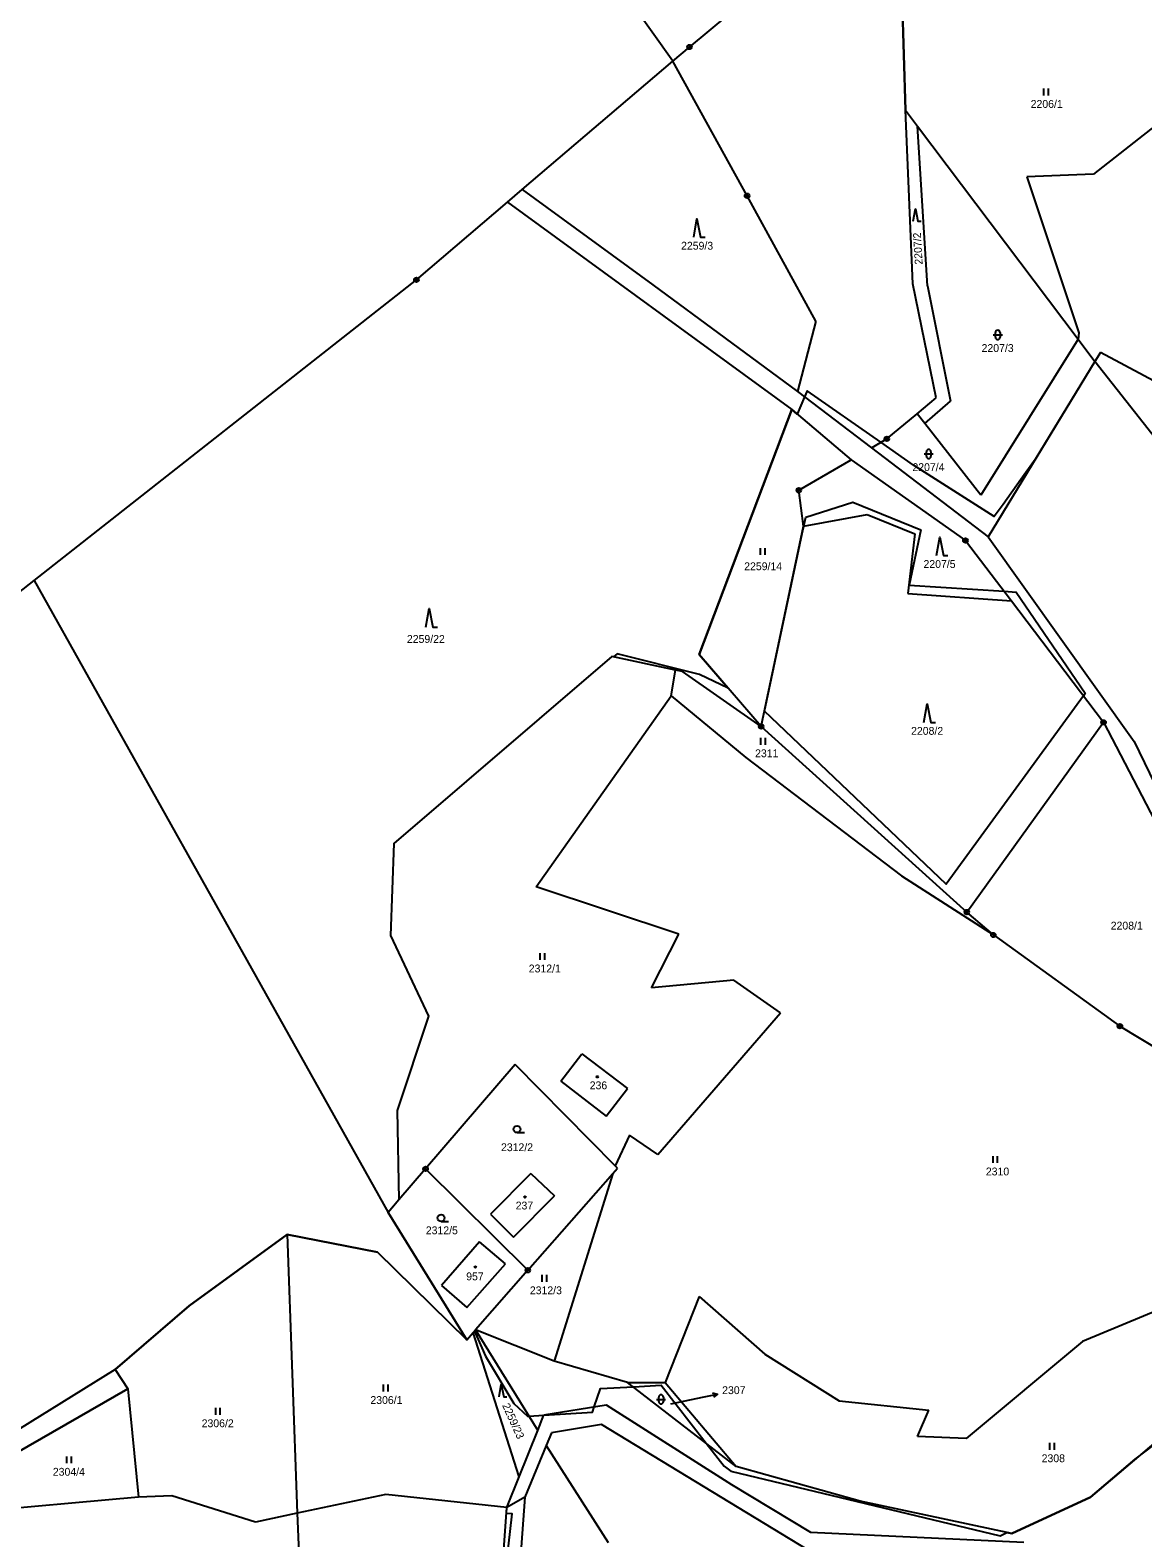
# Model space of a CAD drawing. Extents: x -439246 to -433691, y -1130252 to -1121148.
# Drawn here: x -435681.5 to -435440.1, y -1125991.2 to -1125664.2 of the extents above; entities that cross this region are included whole.
import ezdxf

# ---------------------------------------------------------------- set-up
doc = ezdxf.new("R2010")
doc.units = 0
for name, color, linetype in [('Vrstva 1', 7, 'Continuous'), ('Vrstva 16', 7, 'Continuous'), ('Vrstva 18', 7, 'Continuous'), ('Vrstva 19', 7, 'Continuous'), ('Vrstva 24', 7, 'Continuous'), ('Vrstva 25', 7, 'Continuous'), ('Vrstva 3', 7, 'Continuous'), ('Vrstva 37', 7, 'Continuous'), ('Vrstva 52', 7, 'Continuous'), ('Vrstva 6', 7, 'Continuous')]:
    doc.layers.add(name, color=color, linetype=linetype)

msp = doc.modelspace()

# ---------------------------------------------------------------- linework, layer by layer
at = {"layer": 'Vrstva 1'}
for p, q in [((-435576.26, -1125888.52), (-435595.7, -1125911.15)), ((-435595.7, -1125911.15), (-435601.48, -1125917.89)), ((-435595.7, -1125911.15), (-435573.53, -1125933.14)), ((-435576.65, -1125925.96), (-435567.77, -1125917.01)), ((-435584, -1125926.98), (-435592.25, -1125936.45)), ((-435578.37, -1125931.71), (-435584, -1125926.98)), ((-435586.77, -1125941.22), (-435578.37, -1125931.71)), ((-435592.25, -1125936.45), (-435586.77, -1125941.22))]:
    msp.add_line(p, q, dxfattribs=at)
for points in [[(-435538.46, -1125667.89), (-435508.19, -1125642.69)], [(-435491.59, -1125681.62), (-435492.33, -1125657.5)], [(-435542.09, -1125670.98), (-435538.46, -1125667.89)], [(-435574.76, -1125698.81), (-435542.09, -1125670.98)], [(-435525.97, -1125700.15), (-435542.09, -1125670.98)], [(-435428.66, -1125678.06), (-435450.83, -1125695.45)], [(-435489.99, -1125719.21), (-435491.59, -1125681.62)], [(-435491.59, -1125681.62), (-435488.98, -1125685.08)], [(-435486.84, -1125719.65), (-435488.98, -1125685.08)], [(-435488.98, -1125685.08), (-435454.19, -1125731.24)], [(-435450.83, -1125695.45), (-435465.3, -1125696.06)], [(-435465.3, -1125696.06), (-435454.05, -1125729.85)], [(-435577.96, -1125701.55), (-435574.76, -1125698.81)], [(-435574.76, -1125698.81), (-435546.39, -1125719.49)], [(-435511.08, -1125727.35), (-435525.97, -1125700.15)], [(-435597.71, -1125718.37), (-435577.96, -1125701.55)], [(-435577.96, -1125701.55), (-435516.29, -1125746.48)], [(-435680.62, -1125783.58), (-435597.71, -1125718.37)], [(-435546.39, -1125719.49), (-435515.07, -1125742.59)], [(-435484.97, -1125743.98), (-435489.99, -1125719.21)], [(-435486.84, -1125719.65), (-435481.83, -1125744.68)], [(-435511.08, -1125727.35), (-435515.07, -1125742.59)], [(-435454.05, -1125729.85), (-435454.19, -1125731.24)], [(-435454.19, -1125731.24), (-435475.24, -1125765.04)], [(-435454.19, -1125731.24), (-435450.52, -1125736.1)], [(-435450.52, -1125736.1), (-435473.69, -1125774.07)], [(-435449.32, -1125734.13), (-435450.52, -1125736.1)], [(-435420.97, -1125773.59), (-435450.52, -1125736.1)], [(-435434.6, -1125741.99), (-435449.32, -1125734.13)], [(-435515.07, -1125742.59), (-435499.01, -1125754.8)], [(-435536.34, -1125799.64), (-435516.29, -1125746.48)], [(-435516.29, -1125746.48), (-435503.38, -1125757.39)], [(-435489.1, -1125747.4), (-435484.97, -1125743.98)], [(-435487.42, -1125749.53), (-435481.83, -1125744.68)], [(-435495.67, -1125752.85), (-435489.1, -1125747.4)], [(-435487.42, -1125749.53), (-435489.1, -1125747.4)], [(-435475.24, -1125765.04), (-435487.42, -1125749.53)], [(-435499.01, -1125754.8), (-435495.67, -1125752.85)], [(-435499.01, -1125754.8), (-435473.69, -1125774.07)], [(-435514.75, -1125764.01), (-435503.38, -1125757.39)], [(-435503.38, -1125757.39), (-435478.61, -1125774.89)], [(-435513.71, -1125771.79), (-435514.75, -1125764.01)], [(-435513.71, -1125771.79), (-435499.9, -1125769.24)], [(-435499.9, -1125769.24), (-435489.61, -1125773.47)], [(-435522.92, -1125815.22), (-435513.71, -1125771.79)], [(-435489.61, -1125773.47), (-435491.13, -1125786.36)], [(-435478.61, -1125774.89), (-435468.65, -1125788)], [(-435473.69, -1125774.07), (-435441.99, -1125818.47)], [(-435759.66, -1125845.74), (-435680.62, -1125783.58)], [(-435491.13, -1125786.36), (-435468.65, -1125788)], [(-435468.65, -1125788), (-435448.64, -1125814.32)], [(-435555.28, -1125800.04), (-435602.61, -1125840.57)], [(-435541.53, -1125802.99), (-435555.28, -1125800.04)], [(-435522.92, -1125815.22), (-435536.34, -1125799.64)], [(-435542.42, -1125808.56), (-435541.53, -1125802.99)], [(-435539.96, -1125803.32), (-435541.53, -1125802.99)], [(-435522.92, -1125815.22), (-435539.96, -1125803.32)], [(-435571.69, -1125849.99), (-435542.42, -1125808.56)], [(-435542.42, -1125808.56), (-435526.21, -1125821.97)], [(-435522.92, -1125815.22), (-435478.3, -1125855.47)], [(-435478.3, -1125855.47), (-435448.64, -1125814.32)], [(-435448.64, -1125814.32), (-435432.88, -1125844.58)], [(-435441.99, -1125818.47), (-435430.93, -1125841.35)], [(-435526.21, -1125821.97), (-435492.49, -1125847.63)], [(-435602.61, -1125840.57), (-435603.35, -1125860.57)], [(-435492.49, -1125847.63), (-435472.56, -1125860.44)], [(-435540.76, -1125860.27), (-435571.69, -1125849.99)], [(-435472.56, -1125860.44), (-435478.3, -1125855.47)], [(-435603.35, -1125860.57), (-435595.11, -1125878.07)], [(-435546.74, -1125871.89), (-435540.76, -1125860.27)], [(-435472.56, -1125860.44), (-435445.11, -1125880.21)], [(-435528.87, -1125870.22), (-435546.74, -1125871.89)], [(-435518.73, -1125877.3), (-435528.87, -1125870.22)], [(-435545.35, -1125908.04), (-435518.73, -1125877.3)], [(-435595.11, -1125878.07), (-435601.87, -1125898.53)], [(-435445.11, -1125880.21), (-435427.6, -1125890.78)], [(-435566.36, -1125892.17), (-435561.79, -1125886.2)], [(-435561.79, -1125886.2), (-435551.94, -1125893.75)], [(-435554.6, -1125910.48), (-435576.26, -1125888.52)], [(-435566.36, -1125892.17), (-435556.51, -1125899.71)], [(-435556.51, -1125899.71), (-435551.94, -1125893.75)], [(-435601.87, -1125898.53), (-435601.48, -1125917.89)], [(-435551.5, -1125903.83), (-435554.6, -1125910.48)], [(-435545.35, -1125908.04), (-435551.5, -1125903.83)], [(-435572.86, -1125912.14), (-435581.65, -1125921)], [(-435573.53, -1125933.14), (-435555.12, -1125912.19)], [(-435572.86, -1125912.14), (-435567.77, -1125917.01)], [(-435555.12, -1125912.19), (-435567.84, -1125952.88)], [(-435555.12, -1125912.19), (-435554.08, -1125911.01)], [(-435554.08, -1125911.01), (-435554.6, -1125910.48)], [(-435601.48, -1125917.89), (-435603.81, -1125920.6)], [(-435586.75, -1125948.19), (-435603.81, -1125920.6)], [(-435581.65, -1125921), (-435576.65, -1125925.96)], [(-435646.98, -1125940.87), (-435625.72, -1125925.4)], [(-435625.72, -1125925.4), (-435623.54, -1125985.84)], [(-435625.72, -1125925.4), (-435606.15, -1125929.23)], [(-435606.15, -1125929.23), (-435586.75, -1125948.19)], [(-435573.53, -1125933.14), (-435584.85, -1125946.03)], [(-435536.36, -1125938.82), (-435543.73, -1125957.44)], [(-435536.36, -1125938.82), (-435522.1, -1125951.33)], [(-435663.03, -1125954.68), (-435646.98, -1125940.87)], [(-435436.19, -1125941.5), (-435453.19, -1125948.62)], [(-435585.36, -1125946.62), (-435584.85, -1125946.03)], [(-435567.84, -1125952.88), (-435584.85, -1125946.03)], [(-435586.75, -1125948.19), (-435585.36, -1125946.62)], [(-435575.43, -1125977.94), (-435585.36, -1125946.62)], [(-435453.19, -1125948.62), (-435478.46, -1125969.6)], [(-435522.1, -1125951.33), (-435505.97, -1125961.43)], [(-435663.03, -1125954.68), (-435700.15, -1125977.67)], [(-435663.03, -1125954.68), (-435660.33, -1125958.87)], [(-435551.89, -1125957.44), (-435567.84, -1125952.88)], [(-435695.43, -1125979.03), (-435660.33, -1125958.87)], [(-435660.33, -1125958.87), (-435657.96, -1125982.32)], [(-435528.35, -1125975.68), (-435551.89, -1125957.44)], [(-435551.89, -1125957.44), (-435543.73, -1125957.44)], [(-435543.73, -1125957.44), (-435528.35, -1125975.68)], [(-435423.08, -1125958.3), (-435451.48, -1125982.31)], [(-435570.05, -1125964.52), (-435556.53, -1125962.34)], [(-435556.53, -1125962.34), (-435529.39, -1125979.58)], [(-435505.97, -1125961.43), (-435486.53, -1125963.44)], [(-435571.39, -1125967.86), (-435570.05, -1125964.52)], [(-435489.02, -1125969.17), (-435486.53, -1125963.44)], [(-435575.43, -1125977.94), (-435571.39, -1125967.86)], [(-435568.42, -1125968.42), (-435569.54, -1125971.11)], [(-435557.58, -1125966.57), (-435568.42, -1125968.42)], [(-435512.96, -1125993.68), (-435557.58, -1125966.57)], [(-435569.54, -1125971.11), (-435574.21, -1125982.33)], [(-435478.46, -1125969.6), (-435489.02, -1125969.17)], [(-435578.1, -1125984.61), (-435575.43, -1125977.94)], [(-435501.45, -1125983.23), (-435528.35, -1125975.68)], [(-435604.33, -1125981.77), (-435623.54, -1125985.84)], [(-435578.1, -1125984.61), (-435604.33, -1125981.77)], [(-435529.39, -1125979.58), (-435512.24, -1125989.96)], [(-435657.96, -1125982.32), (-435695.01, -1125985.67)], [(-435650.77, -1125982.03), (-435657.96, -1125982.32)], [(-435632.62, -1125987.76), (-435650.77, -1125982.03)], [(-435580.5, -1126018.03), (-435578.1, -1125984.61)], [(-435574.21, -1125982.33), (-435578.1, -1125984.61)], [(-435574.21, -1125982.33), (-435576.14, -1126008.92)], [(-435468.57, -1125990.23), (-435501.45, -1125983.23)], [(-435451.48, -1125982.31), (-435468.57, -1125990.23)], [(-435623.54, -1125985.84), (-435632.62, -1125987.76)], [(-435623.54, -1125985.84), (-435618.51, -1126106.18)], [(-435512.24, -1125989.96), (-435465.95, -1125992.09)]]:
    msp.add_lwpolyline(points, dxfattribs=at)
at = {"layer": 'Vrstva 16'}
msp.add_line((-435535.31, -1125960.61), (-435532.38, -1125959.99), dxfattribs=at)
for points in [[(-435542.48, -1125962.13), (-435535.31, -1125960.61)], [(-435533.46, -1125959.71), (-435532.38, -1125959.99), (-435533.25, -1125960.68)]]:
    msp.add_lwpolyline(points, dxfattribs=at)
at = {"layer": 'Vrstva 24'}
for centre, radius in [((-435538.46, -1125667.89), 0.5), ((-435538.46, -1125667.89), 0.1), ((-435525.97, -1125700.15), 0.5), ((-435525.97, -1125700.15), 0.1), ((-435597.71, -1125718.37), 0.5), ((-435597.71, -1125718.37), 0.1), ((-435495.67, -1125752.85), 0.5), ((-435495.67, -1125752.85), 0.1), ((-435514.75, -1125764.01), 0.5), ((-435514.75, -1125764.01), 0.1), ((-435478.61, -1125774.89), 0.5), ((-435478.61, -1125774.89), 0.1), ((-435522.92, -1125815.22), 0.5), ((-435522.92, -1125815.22), 0.1), ((-435448.64, -1125814.32), 0.5), ((-435448.64, -1125814.32), 0.1), ((-435478.3, -1125855.47), 0.5), ((-435478.3, -1125855.47), 0.1), ((-435472.56, -1125860.44), 0.5), ((-435472.56, -1125860.44), 0.1), ((-435445.11, -1125880.21), 0.5), ((-435445.11, -1125880.21), 0.1), ((-435595.7, -1125911.15), 0.5), ((-435595.7, -1125911.15), 0.1), ((-435573.53, -1125933.14), 0.5), ((-435573.53, -1125933.14), 0.1)]:
    msp.add_circle(centre, radius, dxfattribs=at)
at = {"layer": 'Vrstva 25'}
for p, q in [((-435461.63, -1125678.39), (-435461.63, -1125676.89)), ((-435460.63, -1125678.39), (-435460.63, -1125676.89)), ((-435472.1, -1125730.82), (-435472.1, -1125729.82)), ((-435471.1, -1125729.82), (-435471.1, -1125730.82)), ((-435472.6, -1125730.32), (-435470.6, -1125730.32)), ((-435487.59, -1125756.14), (-435485.59, -1125756.14)), ((-435487.09, -1125756.64), (-435487.09, -1125755.64)), ((-435486.09, -1125755.64), (-435486.09, -1125756.64)), ((-435523.08, -1125778.04), (-435523.08, -1125776.54)), ((-435522.08, -1125778.04), (-435522.08, -1125776.54)), ((-435522.99, -1125819.19), (-435522.99, -1125817.69)), ((-435521.99, -1125819.19), (-435521.99, -1125817.69)), ((-435570.85, -1125865.85), (-435570.85, -1125864.35)), ((-435569.85, -1125865.85), (-435569.85, -1125864.35)), ((-435575.88, -1125903.3), (-435574.28, -1125903.3)), ((-435472.63, -1125909.87), (-435472.63, -1125908.37)), ((-435471.63, -1125909.87), (-435471.63, -1125908.37)), ((-435592.35, -1125922.55), (-435590.75, -1125922.55)), ((-435570.39, -1125935.64), (-435570.39, -1125934.14)), ((-435569.39, -1125935.64), (-435569.39, -1125934.14)), ((-435604.86, -1125959.43), (-435604.86, -1125957.93)), ((-435603.86, -1125959.43), (-435603.86, -1125957.93)), ((-435545.64, -1125961.13), (-435543.64, -1125961.13)), ((-435545.14, -1125961.63), (-435545.14, -1125960.63)), ((-435544.14, -1125960.63), (-435544.14, -1125961.63)), ((-435641.24, -1125964.47), (-435641.24, -1125962.97)), ((-435640.24, -1125964.47), (-435640.24, -1125962.97)), ((-435460.3, -1125972.06), (-435460.3, -1125970.56)), ((-435459.3, -1125972.06), (-435459.3, -1125970.56)), ((-435673.55, -1125974.99), (-435673.55, -1125973.49)), ((-435672.55, -1125974.99), (-435672.55, -1125973.49))]:
    msp.add_line(p, q, dxfattribs=at)
for points in [[(-435489.93, -1125705.66), (-435489.46, -1125702.98), (-435488.92, -1125705.66), (-435488.25, -1125705.66)], [(-435537.55, -1125709.13), (-435536.85, -1125705.13), (-435536.05, -1125709.13), (-435535.05, -1125709.13)], [(-435484.9, -1125778.15), (-435484.2, -1125774.15), (-435483.4, -1125778.15), (-435482.4, -1125778.15)], [(-435595.65, -1125793.66), (-435594.95, -1125789.66), (-435594.15, -1125793.66), (-435593.15, -1125793.66)], [(-435487.6, -1125814.33), (-435486.9, -1125810.33), (-435486.1, -1125814.33), (-435485.1, -1125814.33)], [(-435579.78, -1125960.59), (-435579.31, -1125957.91), (-435578.77, -1125960.59), (-435578.1, -1125960.59)]]:
    msp.add_lwpolyline(points, dxfattribs=at)
for centre, radius in [((-435558.45, -1125891.19), 0.175), ((-435575.88, -1125902.55), 0.75), ((-435574.16, -1125917.26), 0.175), ((-435592.35, -1125921.8), 0.75), ((-435584.91, -1125932.44), 0.175)]:
    msp.add_circle(centre, radius, dxfattribs=at)
for centre, start, end in [((-435471.6, -1125729.82), 0, 180), ((-435471.6, -1125730.82), 180, 0), ((-435486.59, -1125755.64), 0, 180), ((-435486.59, -1125756.64), 180, 0), ((-435544.64, -1125960.63), 0, 180), ((-435544.64, -1125961.63), 180, 0)]:
    msp.add_arc(centre, 0.5, start, end, dxfattribs=at)
at = {"layer": 'Vrstva 3'}
for points in [[(-435566.36, -1125892.17), (-435561.79, -1125886.2)], [(-435561.79, -1125886.2), (-435551.94, -1125893.75)], [(-435566.36, -1125892.17), (-435556.51, -1125899.71)], [(-435556.51, -1125899.71), (-435551.94, -1125893.75)], [(-435572.86, -1125912.14), (-435581.65, -1125921)], [(-435572.86, -1125912.14), (-435567.77, -1125917.01)], [(-435576.65, -1125925.96), (-435567.77, -1125917.01)], [(-435581.65, -1125921), (-435576.65, -1125925.96)], [(-435584, -1125926.98), (-435592.25, -1125936.45)], [(-435578.37, -1125931.71), (-435584, -1125926.98)], [(-435586.77, -1125941.22), (-435578.37, -1125931.71)], [(-435592.25, -1125936.45), (-435586.77, -1125941.22)]]:
    msp.add_lwpolyline(points, dxfattribs=at)
at = {"layer": 'Vrstva 37'}
for centre in [(-435558.45, -1125891.19), (-435574.16, -1125917.26), (-435584.91, -1125932.44)]:
    msp.add_circle(centre, 0.175, dxfattribs=at)
at = {"layer": 'Vrstva 52'}
for points in [[(-435492.33, -1125657.5), (-435491.59, -1125681.62), (-435488.98, -1125685.08), (-435454.19, -1125731.24), (-435450.52, -1125736.1), (-435463.49, -1125757.35), (-435466.6, -1125761.7), (-435470.46, -1125767.09), (-435472.35, -1125769.72), (-435489.85, -1125758.57), (-435496.96, -1125753.6), (-435512.93, -1125742.44), (-435513.5, -1125743.78), (-435515.08, -1125747.5), (-435516.29, -1125746.48), (-435536.34, -1125799.64), (-435530.08, -1125806.91), (-435536.29, -1125803.94), (-435554.18, -1125799.47), (-435554.92, -1125800.12), (-435555.28, -1125800.04), (-435602.61, -1125840.57), (-435603.35, -1125860.57), (-435595.11, -1125878.07), (-435601.87, -1125898.53), (-435601.48, -1125917.89), (-435603.04, -1125919.7), (-435603.81, -1125920.6), (-435586.75, -1125948.19), (-435606.15, -1125929.23), (-435625.72, -1125925.4), (-435646.98, -1125940.87), (-435663.03, -1125954.68), (-435660.33, -1125958.87), (-435695.43, -1125979.03)], [(-435453.02, -1125808.56), (-435482.82, -1125849.44), (-435522.22, -1125811.93), (-435514.05, -1125773.41), (-435513.9, -1125772.73), (-435513.69, -1125771.78), (-435513.25, -1125769.86), (-435503.02, -1125766.62), (-435488.3, -1125772.6)], [(-435488.3, -1125772.6), (-435490.8, -1125784.58), (-435470.24, -1125785.9), (-435467.6, -1125786.07), (-435452.63, -1125808.03), (-435453.02, -1125808.56)], [(-435578.51, -1126000), (-435576.91, -1125985.92), (-435578.19, -1125985.85), (-435578.1, -1125984.61), (-435575.43, -1125977.94), (-435585.36, -1125946.62), (-435585.12, -1125946.35), (-435582.73, -1125951.78), (-435576.55, -1125962.01), (-435573.57, -1125964.78), (-435573.3, -1125964.76), (-435570.07, -1125964.57), (-435559.51, -1125963.93), (-435559.12, -1125962.76), (-435557.8, -1125958.81), (-435550.64, -1125958.41), (-435544.63, -1125958.07), (-435534.85, -1125970.64), (-435530.96, -1125975.64), (-435529.47, -1125976.71), (-435471.05, -1125990.7), (-435469.6, -1125990.01), (-435468.57, -1125990.23), (-435451.48, -1125982.31), (-435441.81, -1125974.13), (-435420.83, -1125958.17)]]:
    msp.add_lwpolyline(points, dxfattribs=at)
at = {"layer": 'Vrstva 6'}
for points in [[(-435542.09, -1125670.98), (-435563.43, -1125640.97)], [(-435680.62, -1125783.58), (-435603.81, -1125920.6)], [(-435584.85, -1125946.03), (-435571.39, -1125967.86)], [(-435569.54, -1125971.11), (-435556.12, -1125992.15)]]:
    msp.add_lwpolyline(points, dxfattribs=at)

# ---------------------------------------------------------------- texts
at = {"layer": 'Vrstva 16'}
msp.add_text('2307', height=1.7, dxfattribs=at).set_placement((-435531.38, -1125959.99))
at = {"layer": 'Vrstva 18'}
for s, height, p in [('2206/1', 1.7, (-435464.46, -1125681.09)), ('2259/3', 1.7, (-435540.29, -1125711.83)), ('2207/3', 1.7, (-435475.11, -1125734.02)), ('2207/4', 1.7, (-435490.11, -1125759.84)), ('2207/5', 1.7, (-435487.71, -1125780.85)), ('2259/14', 1.7, (-435526.6, -1125781.34)), ('2259/22', 1.7, (-435599.76, -1125797.1)), ('2208/2', 1.7, (-435490.4, -1125817.03)), ('2311', 1.7, (-435524.24, -1125821.89)), ('2208/1', 1.7, (-435447.1, -1125859.26)), ('2312/1', 1.7, (-435573.33, -1125868.55)), ('2312/2', 1.7, (-435579.35, -1125907.31)), ('2310', 1.7, (-435474.18, -1125912.57)), ('2312/5', 1.7, (-435595.66, -1125925.33)), ('2312/3', 1.7, (-435573.09, -1125938.34)), ('2306/1', 1.7, (-435607.68, -1125962.13)), ('2307', 0.1, (-435542.63, -1125962.13)), ('2306/2', 1.7, (-435644.28, -1125967.17)), ('2308', 1.7, (-435462.08, -1125974.76)), ('2304/4', 1.7, (-435676.56, -1125977.69))]:
    msp.add_text(s, height=height, dxfattribs=at).set_placement(p)
for s, rotation, p in [('2207/2', 93.2593, (-435487.89, -1125715.02)), ('2259/23', 294.2975, (-435579.14, -1125962.42))]:
    msp.add_text(s, height=1.7, rotation=rotation, dxfattribs=at).set_placement(p)
at = {"layer": 'Vrstva 19'}
for s, p in [('236', (-435560.11, -1125893.89)), ('237', (-435576.17, -1125919.95)), ('957', (-435586.9, -1125935.31))]:
    msp.add_text(s, height=1.7, dxfattribs=at).set_placement(p)

doc.saveas('drawing.dxf')
